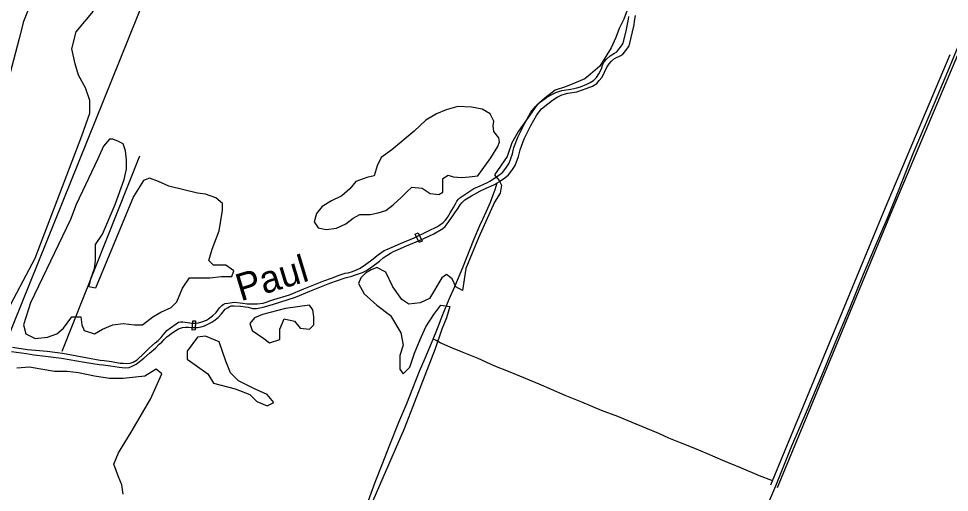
# Model space of a CAD drawing. Extents: x 3329332 to 3367211, y 631066 to 656469.
# Drawn here: x 3339674 to 3343639, y 651272 to 653290 of the extents above; entities that cross this region are included whole.
import ezdxf

# ---------------------------------------------------------------- set-up
doc = ezdxf.new("R2010")
doc.units = 0
for name, color, linetype in [('V-BRDG-OTLN', 7, 'Continuous'), ('V-DTCH-CNTR', 7, 'Continuous'), ('V-RIVR-IDEN', 7, 'Continuous'), ('V-ROAD-CNTR', 7, 'Continuous'), ('V-SITE-VEGE', 7, 'Continuous'), ('V-TOPO-SHOR', 7, 'Continuous')]:
    doc.layers.add(name, color=color, linetype=linetype)

msp = doc.modelspace()

# ---------------------------------------------------------------- linework, layer by layer
at = {"layer": 'V-BRDG-OTLN'}
for points in [[(3341380.1, 652335.7), (3341362.9, 652371), (3341375.9, 652377.5), (3341393.1, 652341.2)], [(3340413.5, 651963.4), (3340415.4, 652002.4), (3340427.6, 652002.6), (3340425.3, 651963.7)]]:
    msp.add_lwpolyline(points, close=True, dxfattribs=at)
at = {"layer": 'V-DTCH-CNTR'}
msp.add_lwpolyline([(3343685.2, 653194), (3343631.2, 653063.1), (3343551.1, 652873.8), (3343482.8, 652713.8), (3343422.8, 652561.2), (3343377.1, 652445.5), (3343318.3, 652311.2), (3343271.4, 652200.2), (3343212, 652052.3), (3343151.5, 651906.9), (3343101, 651784.7), (3343033.3, 651624.1), (3342966.9, 651469.3), (3342898, 651298.1), (3342828, 651136.8), (3342754.9, 650962.1), (3342680.7, 650785.1), (3342631.5, 650670.6), (3342576.2, 650529.8), (3342502, 650356.8), (3342429, 650186.2)], dxfattribs=at)
at = {"layer": 'V-ROAD-CNTR'}
for points in [[(3343640.8, 653135.7), (3343365.5, 652483.2), (3342877.1, 651302.3)], [(3343672.9, 653134.6), (3343393.2, 652471.6), (3342904.8, 651290.9)]]:
    msp.add_lwpolyline(points, dxfattribs=at)
at = {"layer": 'V-SITE-VEGE'}
for p, q in [((3339743.8, 653399.2), (3339695.2, 653277.4)), ((3339919.1, 653233.5), (3339992.2, 653321.2)), ((3342266.1, 653326.1), (3342251.5, 653287.1)), ((3339695.2, 653277.4), (3339675.7, 653204.3)), ((3342251.5, 653287.1), (3342232, 653248.1)), ((3339899.7, 653160.4), (3339919.1, 653233.5)), ((3342232, 653248.1), (3342217.4, 653209.2)), ((3339675.7, 653204.3), (3339636.7, 653053.2)), ((3342217.4, 653209.2), (3342197.9, 653165.3)), ((3339914.3, 653097.1), (3339899.7, 653160.4)), ((3342197.9, 653165.3), (3342149.2, 653087.3)), ((3339928.9, 653048.3), (3339914.3, 653097.1)), ((3342149.2, 653087.3), (3342110.3, 653053.2)), ((3339958.1, 652994.7), (3339928.9, 653048.3)), ((3342085.9, 653033.7), (3342042.1, 653014.2)), ((3342110.3, 653053.2), (3342085.9, 653033.7)), ((3339977.6, 652941.1), (3339958.1, 652994.7)), ((3341959.3, 652985), (3341915.5, 652950.9)), ((3342003.2, 652999.6), (3341959.3, 652985)), ((3342042.1, 653014.2), (3342003.2, 652999.6)), ((3339977.6, 652887.5), (3339977.6, 652941.1)), ((3341915.5, 652950.9), (3341881.4, 652921.6)), ((3341495.5, 652900.9), (3341454.2, 652883.9)), ((3341544.2, 652915.6), (3341495.5, 652900.9)), ((3341602.7, 652913.1), (3341544.2, 652915.6)), ((3341648.9, 652903.4), (3341602.7, 652913.1)), ((3341683, 652883.9), (3341648.9, 652903.4)), ((3341881.4, 652921.6), (3341862, 652892.4)), ((3339943.5, 652790.1), (3339977.6, 652887.5)), ((3341454.2, 652883.9), (3341407.9, 652857.1)), ((3341697.6, 652852.2), (3341683, 652883.9)), ((3341862, 652892.4), (3341803.5, 652809.6)), ((3341407.9, 652857.1), (3341359.2, 652810.8)), ((3341695.2, 652832.7), (3341697.6, 652852.2)), ((3341697.6, 652808.4), (3341695.2, 652832.7)), ((3339743.8, 652268.7), (3339943.5, 652790.1)), ((3341359.2, 652810.8), (3341264.3, 652730.4)), ((3341719.5, 652781.6), (3341697.6, 652808.4)), ((3341803.5, 652809.6), (3341774.3, 652760.8)), ((3340036, 652746.2), (3340011.7, 652692.6)), ((3340060.3, 652775.5), (3340036, 652746.2)), ((3340075, 652775.5), (3340060.3, 652775.5)), ((3340099.3, 652765.7), (3340075, 652775.5)), ((3340118.8, 652756), (3340099.3, 652765.7)), ((3340128.5, 652726.7), (3340118.8, 652756)), ((3341685.5, 652696.3), (3341714.7, 652745)), ((3341714.7, 652745), (3341722, 652764.5)), ((3341722, 652764.5), (3341719.5, 652781.6)), ((3341774.3, 652760.8), (3341754.8, 652702.4)), ((3340133.4, 652687.7), (3340128.5, 652726.7)), ((3341264.3, 652730.4), (3341218, 652698.7)), ((3340011.7, 652692.6), (3339919.1, 652497.7)), ((3340133.4, 652648.8), (3340133.4, 652687.7)), ((3341218, 652698.7), (3341201, 652662.2)), ((3341629.5, 652620.7), (3341685.5, 652696.3)), ((3341754.8, 652702.4), (3341701.3, 652624.4)), ((3340123.6, 652604.9), (3340133.4, 652648.8)), ((3341201, 652662.2), (3341188.8, 652620.7)), ((3341701.3, 652624.4), (3341720.7, 652600)), ((3340084.7, 652497.7), (3340123.6, 652604.9)), ((3340206.4, 652600), (3340162.6, 652531.8)), ((3340230.8, 652609.8), (3340206.4, 652600)), ((3340269.7, 652595.2), (3340230.8, 652609.8)), ((3340313.5, 652575.7), (3340269.7, 652595.2)), ((3341110.9, 652596.4), (3341084.1, 652564.7)), ((3341157.1, 652613.4), (3341110.9, 652596.4)), ((3341188.8, 652620.7), (3341157.1, 652613.4)), ((3341480.9, 652608.6), (3341502.9, 652623.2)), ((3341480.9, 652550.1), (3341480.9, 652608.6)), ((3341502.9, 652623.2), (3341524.8, 652615.9)), ((3341524.8, 652615.9), (3341561.3, 652613.4)), ((3341561.3, 652613.4), (3341592.9, 652615.9)), ((3341592.9, 652615.9), (3341629.5, 652620.7)), ((3341720.7, 652600), (3341730.5, 652580.5)), ((3340435.3, 652546.4), (3340313.5, 652575.7)), ((3340469.4, 652541.6), (3340435.3, 652546.4)), ((3341084.1, 652564.7), (3341050, 652535.5)), ((3341303.2, 652528.2), (3341327.6, 652552.5)), ((3341327.6, 652552.5), (3341349.5, 652572)), ((3341349.5, 652572), (3341393.3, 652567.1)), ((3341393.3, 652567.1), (3341427.4, 652545.2)), ((3341427.4, 652545.2), (3341463.9, 652540.3)), ((3341463.9, 652540.3), (3341480.9, 652550.1)), ((3341725.6, 652546.4), (3341701.3, 652507.4)), ((3341730.5, 652580.5), (3341725.6, 652546.4)), ((3340162.6, 652531.8), (3340001.9, 652142)), ((3340513.2, 652526.9), (3340469.4, 652541.6)), ((3340542.4, 652502.6), (3340513.2, 652526.9)), ((3341006.2, 652513.5), (3340967.2, 652489.2)), ((3341050, 652535.5), (3341006.2, 652513.5)), ((3341269.1, 652496.5), (3341303.2, 652528.2)), ((3341701.3, 652507.4), (3341633.1, 652356.4)), ((3339919.1, 652497.7), (3339894.8, 652434.4)), ((3340031.1, 652371), (3340084.7, 652497.7)), ((3340527.8, 652385.6), (3340542.4, 652473.3)), ((3340542.4, 652473.3), (3340542.4, 652502.6)), ((3340967.2, 652489.2), (3340942.9, 652459.9)), ((3341205.8, 652462.4), (3341237.5, 652472.1)), ((3341237.5, 652472.1), (3341269.1, 652496.5)), ((3339894.8, 652434.4), (3339724.4, 652078.6)), ((3340942.9, 652459.9), (3340933.2, 652423.4)), ((3341067.1, 652416.1), (3341098.7, 652440.4)), ((3341098.7, 652440.4), (3341127.9, 652455.1)), ((3341127.9, 652455.1), (3341171.7, 652455.1)), ((3341171.7, 652455.1), (3341205.8, 652462.4)), ((3340498.6, 652307.7), (3340527.8, 652385.6)), ((3340933.2, 652423.4), (3340950.2, 652399)), ((3340950.2, 652399), (3340984.3, 652391.7)), ((3340984.3, 652391.7), (3341028.1, 652396.6)), ((3341028.1, 652396.6), (3341067.1, 652416.1)), ((3340001.9, 652327.1), (3340031.1, 652371)), ((3341633.1, 652356.4), (3341579.5, 652224.8)), ((3340001.9, 652258.9), (3340001.9, 652327.1)), ((3340484, 652258.9), (3340498.6, 652307.7)), ((3339602.6, 652000.7), (3339743.8, 652268.7)), ((3339997, 652224.8), (3340001.9, 652258.9)), ((3340503.4, 652239.4), (3340484, 652258.9)), ((3340557, 652239.4), (3340503.4, 652239.4)), ((3340591.1, 652215.1), (3340557, 652239.4)), ((3341199.7, 652229.7), (3341175.4, 652219.9)), ((3341238.7, 652210.2), (3341199.7, 652229.7)), ((3339982.4, 652185.8), (3339997, 652224.8)), ((3340488.8, 652185.8), (3340537.5, 652190.7)), ((3340537.5, 652190.7), (3340581.4, 652190.7)), ((3340581.4, 652190.7), (3340591.1, 652215.1)), ((3341151.1, 652205.3), (3341131.6, 652185.8)), ((3341175.4, 652219.9), (3341151.1, 652205.3)), ((3341267.9, 652146.8), (3341238.7, 652210.2)), ((3341496.8, 652200.5), (3341477.3, 652185.8)), ((3341521.1, 652181), (3341496.8, 652200.5)), ((3341579.5, 652224.8), (3341564.9, 652132.2)), ((3339972.7, 652146.8), (3339982.4, 652185.8)), ((3340372, 652142), (3340401.2, 652185.8)), ((3340401.2, 652185.8), (3340488.8, 652185.8)), ((3341131.6, 652185.8), (3341121.8, 652161.5)), ((3341121.8, 652161.5), (3341146.2, 652117.6)), ((3341477.3, 652185.8), (3341423.7, 652098.1)), ((3341535.7, 652146.8), (3341521.1, 652181)), ((3340001.9, 652142), (3339972.7, 652146.8)), ((3340347.6, 652083.5), (3340372, 652142)), ((3341146.2, 652117.6), (3341199.7, 652068.9)), ((3341306.9, 652093.2), (3341267.9, 652146.8)), ((3341564.9, 652132.2), (3341535.7, 652146.8)), ((3339724.4, 652078.6), (3339695.2, 651986)), ((3340323.3, 652059.1), (3340347.6, 652083.5)), ((3340912.5, 652068.9), (3340810.2, 652054.3)), ((3340927.1, 652049.4), (3340912.5, 652068.9)), ((3341199.7, 652068.9), (3341258.2, 652025)), ((3341336.1, 652073.8), (3341306.9, 652093.2)), ((3341384.8, 652078.6), (3341336.1, 652073.8)), ((3341423.7, 652098.1), (3341384.8, 652078.6)), ((3341443.2, 652029.9), (3341472.4, 652068.9)), ((3341472.4, 652068.9), (3341511.4, 652064)), ((3340245.4, 652020.2), (3340279.5, 652039.6)), ((3340279.5, 652039.6), (3340323.3, 652059.1)), ((3340712.8, 652029.9), (3340678.7, 652015.3)), ((3340810.2, 652054.3), (3340712.8, 652029.9)), ((3340931.9, 652020.2), (3340927.1, 652049.4)), ((3341409.1, 651976.3), (3341443.2, 652029.9)), ((3341511.4, 652064), (3341496.8, 652015.3)), ((3339865.6, 651971.4), (3339899.7, 652020.2)), ((3339899.7, 652020.2), (3339938.6, 652020.2)), ((3339938.6, 652020.2), (3339943.5, 651986)), ((3340075, 651986), (3340118.8, 651990.9)), ((3340118.8, 651990.9), (3340167.5, 651986)), ((3340201.6, 651986), (3340245.4, 652020.2)), ((3340678.7, 652015.3), (3340659.3, 651990.9)), ((3340659.3, 651990.9), (3340669, 651961.7)), ((3340785.9, 651966.5), (3340805.3, 652010.4)), ((3340805.3, 652010.4), (3340849.2, 652000.7)), ((3340849.2, 652000.7), (3340873.5, 651971.4)), ((3340931.9, 651986), (3340931.9, 652020.2)), ((3341258.2, 652025), (3341302, 651951.9)), ((3341496.8, 652015.3), (3341477.3, 651966.5)), ((3339695.2, 651986), (3339704.9, 651947.1)), ((3339836.4, 651947.1), (3339865.6, 651971.4)), ((3339943.5, 651986), (3339953.2, 651961.7)), ((3339953.2, 651961.7), (3339997, 651947.1)), ((3339997, 651947.1), (3340031.1, 651966.5)), ((3340031.1, 651966.5), (3340075, 651986)), ((3340167.5, 651986), (3340201.6, 651986)), ((3340669, 651961.7), (3340717.7, 651927.6)), ((3340785.9, 651922.7), (3340785.9, 651966.5)), ((3340873.5, 651971.4), (3340912.5, 651966.5)), ((3340912.5, 651966.5), (3340931.9, 651986)), ((3341302, 651951.9), (3341311.7, 651898.3)), ((3341384.8, 651922.7), (3341409.1, 651976.3)), ((3341477.3, 651966.5), (3341448.1, 651883.7)), ((3339704.9, 651947.1), (3339743.8, 651927.6)), ((3339743.8, 651927.6), (3339797.4, 651932.4)), ((3339797.4, 651932.4), (3339836.4, 651947.1)), ((3340435.3, 651932.4), (3340391.5, 651874)), ((3340469.4, 651937.3), (3340435.3, 651932.4)), ((3340527.8, 651912.9), (3340469.4, 651937.3)), ((3340557, 651830.1), (3340527.8, 651912.9)), ((3340717.7, 651927.6), (3340742, 651908.1)), ((3340742, 651908.1), (3340785.9, 651922.7)), ((3341360.4, 651864.2), (3341384.8, 651922.7)), ((3340391.5, 651874), (3340391.5, 651839.9)), ((3341311.7, 651898.3), (3341297.1, 651854.5)), ((3341448.1, 651883.7), (3341316.6, 651542.6)), ((3340391.5, 651839.9), (3340479.1, 651776.5)), ((3341297.1, 651854.5), (3341297.1, 651796)), ((3341341, 651805.7), (3341360.4, 651864.2)), ((3339719.5, 651805.8), (3339665.9, 651800.9)), ((3339768.2, 651796), (3339719.5, 651805.8)), ((3339826.6, 651786.3), (3339768.2, 651796)), ((3340260, 651796), (3340211.3, 651766.8)), ((3340284.3, 651776.5), (3340260, 651796)), ((3340576.5, 651781.4), (3340557, 651830.1)), ((3341297.1, 651796), (3341311.7, 651776.5)), ((3341311.7, 651776.5), (3341341, 651805.7)), ((3339880.2, 651786.3), (3339826.6, 651786.3)), ((3339928.9, 651781.4), (3339880.2, 651786.3)), ((3339997, 651766.8), (3339928.9, 651781.4)), ((3340060.3, 651757), (3339997, 651766.8)), ((3340118.8, 651757), (3340060.3, 651757)), ((3340211.3, 651766.8), (3340118.8, 651757)), ((3340235.6, 651669.3), (3340284.3, 651776.5)), ((3340479.1, 651776.5), (3340503.4, 651737.5)), ((3340610.6, 651747.3), (3340576.5, 651781.4)), ((3340503.4, 651737.5), (3340596, 651713.2)), ((3340596, 651713.2), (3340659.3, 651688.8)), ((3340678.7, 651713.2), (3340610.6, 651747.3)), ((3340732.3, 651688.8), (3340678.7, 651713.2)), ((3340659.3, 651688.8), (3340688.5, 651659.6)), ((3340761.5, 651654.7), (3340732.3, 651688.8)), ((3340152.9, 651528), (3340235.6, 651669.3)), ((3340688.5, 651659.6), (3340732.3, 651640.1)), ((3340732.3, 651640.1), (3340761.5, 651654.7)), ((3340099.3, 651440.3), (3340152.9, 651528)), ((3341316.6, 651542.6), (3341141.3, 651143)), ((3340079.8, 651391.6), (3340099.3, 651440.3)), ((3340099.3, 651338), (3340079.8, 651391.6)), ((3340113.9, 651303.8), (3340099.3, 651338)), ((3340118.8, 651264.9), (3340113.9, 651303.8))]:
    msp.add_line(p, q, dxfattribs=at)
at = {"layer": 'V-TOPO-SHOR'}
for p, q in [((3339617.5, 651905.1), (3340718.9, 654637.1)), ((3339859.9, 651873.2), (3340189.5, 652705.8)), ((3341452.4, 651918.4), (3341439.8, 651924.8))]:
    msp.add_line(p, q, dxfattribs=at)
for points in [[(3340344.5, 651990.2), (3340354.4, 651996.3), (3340363.1, 651998.1), (3340372.8, 651998.2), (3340393.8, 651994.8), (3340412.7, 651993.1), (3340426.6, 651993), (3340439.8, 651994.5), (3340453.8, 651998.6), (3340473.9, 652005.4), (3340483, 652010.3), (3340500.3, 652023.4), (3340515.2, 652038.5), (3340530.1, 652058.5), (3340538.9, 652067.9), (3340545.1, 652072.2), (3340554, 652076.4), (3340564.3, 652078.4), (3340593, 652082), (3340617.6, 652079), (3340629.5, 652077.7), (3340647.6, 652074.7), (3340661.6, 652074.2), (3340689.9, 652074.9), (3340715.8, 652078), (3340761, 652092.9), (3340827.3, 652113.9), (3340889, 652138.6), (3340973.4, 652172.6), (3341005.9, 652184.4), (3341039.2, 652196.5), (3341065.2, 652205), (3341078.3, 652207.4), (3341095.6, 652212.6), (3341112.5, 652219.1), (3341129.3, 652226.8), (3341152, 652242.3), (3341184.6, 652266.7), (3341201.5, 652281), (3341231.6, 652301.8), (3341245.6, 652308.3), (3341265, 652316.8), (3341300.4, 652332.2), (3341359.2, 652356.5), (3341416.5, 652384.1), (3341457.6, 652404.4), (3341466.3, 652409.7), (3341482.8, 652421.9), (3341490.6, 652429.2), (3341500.6, 652443.1), (3341512.6, 652462), (3341526.7, 652484.5), (3341534.2, 652501.3), (3341540.4, 652512.3), (3341547, 652521.3), (3341552.8, 652526.2), (3341579.1, 652544), (3341613.4, 652565.7), (3341639.3, 652577.5), (3341671.8, 652592.1), (3341681.3, 652596.9), (3341696.6, 652606.7), (3341719.2, 652622.6), (3341734.5, 652634.8), (3341749.4, 652652.8), (3341763.1, 652674.5), (3341777.6, 652713.4), (3341784, 652740.5), (3341801.9, 652787.6), (3341830.5, 652845), (3341855.4, 652890.8), (3341876.1, 652915.7), (3341901.7, 652937.4), (3341922.7, 652953.3), (3341942.5, 652965.5), (3341962.3, 652975.2), (3341988.2, 652982.9), (3342026.4, 652988.8), (3342051.5, 652994.4), (3342067.1, 652999.7), (3342094.7, 653010.2), (3342109.1, 653017.1), (3342122.7, 653026.1), (3342135.1, 653038.7), (3342145.1, 653054.7), (3342156.7, 653076.4), (3342161.7, 653090.7), (3342168.8, 653105.5), (3342178.3, 653116.9), (3342194.4, 653130.4), (3342212.9, 653142.2), (3342221.6, 653148.3), (3342231.1, 653158.9), (3342237.7, 653168.3), (3342247.2, 653181.8), (3342251.8, 653195.7), (3342262.8, 653243.7), (3342269.5, 653273.7), (3342271.6, 653287.2), (3342272.9, 653298.3)], [(3341712.7, 652590.1), (3341722.4, 652596.3), (3341745, 652612.2), (3341760.3, 652624.4), (3341775.2, 652642.4), (3341788.9, 652664.1), (3341803.5, 652703), (3341809.8, 652730.1), (3341827.7, 652777.2), (3341856.4, 652834.5), (3341881.3, 652880.4), (3341901.9, 652905.3), (3341927.5, 652927), (3341948.5, 652942.9), (3341968.3, 652955.1), (3341988.1, 652964.8), (3342014, 652972.5), (3342052.2, 652978.4), (3342076.3, 652986.5), (3342091.2, 652991.4), (3342118.1, 653001.9), (3342136.4, 653013.6), (3342146.2, 653025.4), (3342157.9, 653039.5), (3342165, 653052), (3342174.5, 653071.2), (3342181.3, 653084.5), (3342189, 653096.8), (3342198.9, 653108.6), (3342212.2, 653119.3), (3342238.7, 653131.8), (3342247.4, 653137.9), (3342256.9, 653148.5), (3342263.5, 653157.9), (3342273, 653171.4), (3342277.6, 653185.3), (3342288.6, 653233.3), (3342295.3, 653263.3), (3342297.4, 653276.8), (3342298.7, 653287.9), (3342302.1, 653302.2)], [(3340355.5, 651967.8), (3340371.4, 651973.4), (3340385, 651975.8), (3340395.5, 651976), (3340415, 651974.7), (3340436, 651974.3), (3340451, 651977.4), (3340465.6, 651981.3), (3340479.6, 651988.2), (3340496.6, 651996.4), (3340505.7, 652002.7), (3340523.7, 652016.8), (3340538.2, 652032.6), (3340553.1, 652051.6), (3340563.3, 652057.5), (3340570.5, 652062.1), (3340579.8, 652066), (3340591.1, 652066.6), (3340618.8, 652064.9), (3340640.3, 652061.9), (3340651.5, 652060.7), (3340670.2, 652054.9), (3340687.3, 652054.4), (3340716, 652060.3), (3340741.6, 652067.6), (3340786.9, 652082.5), (3340853.1, 652103.5), (3340914.8, 652128.2), (3340999.2, 652162.2), (3341031.7, 652173.9), (3341065, 652186.1), (3341093.4, 652193.1), (3341104.1, 652196.9), (3341121.4, 652202.2), (3341138.3, 652208.7), (3341155.2, 652216.4), (3341177.8, 652231.8), (3341210.4, 652256.3), (3341227.3, 652270.6), (3341257.4, 652291.3), (3341271.4, 652297.8), (3341290.8, 652306.4), (3341326.2, 652321.8), (3341385, 652346.1), (3341442.3, 652373.7), (3341480.3, 652395.4), (3341490.7, 652403.8), (3341503.4, 652420.6), (3341511.7, 652433.8), (3341520.5, 652445), (3341531.5, 652462), (3341545.6, 652481.8), (3341554.8, 652496.1), (3341561.7, 652504.7), (3341569.3, 652512.7), (3341575.1, 652518.3), (3341602.5, 652535.4), (3341639.2, 652555.3), (3341665.1, 652567.1), (3341697.6, 652581.7), (3341707.1, 652586.5), (3341712.7, 652590.1)], [(3341163.9, 651237.3), (3341192.5, 651315.9), (3341222.9, 651390.9), (3341255.8, 651475), (3341293.6, 651570.9), (3341327.5, 651650.5), (3341353.6, 651715.1), (3341381.9, 651788.8), (3341405.9, 651843.7), (3341432.7, 651907.6), (3341439.8, 651924.8), (3341455.3, 651962.5), (3341480.7, 652028.9), (3341508.3, 652094.9), (3341531.9, 652149.4), (3341566.1, 652229.3), (3341584.9, 652276.6), (3341596.2, 652305.1), (3341613.9, 652351.6), (3341639.2, 652407.9), (3341651.9, 652436.1), (3341667.5, 652469.7), (3341683.3, 652508), (3341694.7, 652538.5), (3341703.2, 652562.2), (3341712.7, 652590.1)], [(3339648.2, 651890.2), (3339711.4, 651880.8), (3339746.3, 651877.3), (3339796, 651873.8), (3339860.8, 651865.2), (3339960.5, 651845.7), (3340021.6, 651835.1), (3340037.6, 651833), (3340068.8, 651828.7), (3340106.2, 651822.7), (3340118.5, 651821.8), (3340132.8, 651820.9), (3340148.5, 651822.5), (3340162, 651826.9), (3340179.3, 651836.7), (3340207, 651863.2), (3340230.5, 651886.5), (3340255.7, 651908.9), (3340268.1, 651918.7), (3340281.3, 651932.2), (3340289.2, 651943.2), (3340298.8, 651954.6), (3340304.5, 651960.9), (3340320.1, 651972.6), (3340344.5, 651990.2)], [(3339644, 651872.1), (3339707.2, 651862.7), (3339739.2, 651857.9), (3339787.9, 651852.2), (3339855.8, 651844), (3339953.8, 651825.9), (3340017.4, 651817), (3340033.4, 651814.9), (3340064.5, 651810.6), (3340101.9, 651804.6), (3340114.2, 651803.8), (3340128.6, 651802.8), (3340144.2, 651804.4), (3340157.8, 651808.8), (3340175.1, 651818.6), (3340207.6, 651843.4), (3340230.8, 651864.9), (3340256.3, 651886), (3340272.9, 651903), (3340283.3, 651912), (3340294.3, 651922.7), (3340305.3, 651933.7), (3340315.1, 651942), (3340331.9, 651954.8), (3340355.5, 651967.8)], [(3342882.8, 651322.1), (3342829.3, 651343), (3342753.2, 651375.4), (3342673, 651408.3), (3342608.4, 651435.8), (3342554.5, 651458.8), (3342493.4, 651482.8), (3342443, 651502.6), (3342400.9, 651522.7), (3342345.4, 651545.3), (3342287.7, 651568.9), (3342225.8, 651594.7), (3342157.4, 651620.5), (3342072.6, 651655.5), (3342002.1, 651685.1), (3341943.7, 651709.5), (3341890.9, 651732.1), (3341832.5, 651756.4), (3341761.3, 651786.1), (3341702.9, 651809.7), (3341631.4, 651841.8), (3341567.1, 651867.3), (3341521.9, 651886.3), (3341470.2, 651909.3), (3341452.4, 651918.4)]]:
    msp.add_lwpolyline(points, dxfattribs=at)

# ---------------------------------------------------------------- texts
at = {"layer": 'V-RIVR-IDEN'}
msp.add_text('Paul', height=116, rotation=16.7711, dxfattribs=at).set_placement((3340619.6, 652085.2))

doc.saveas('drawing.dxf')
